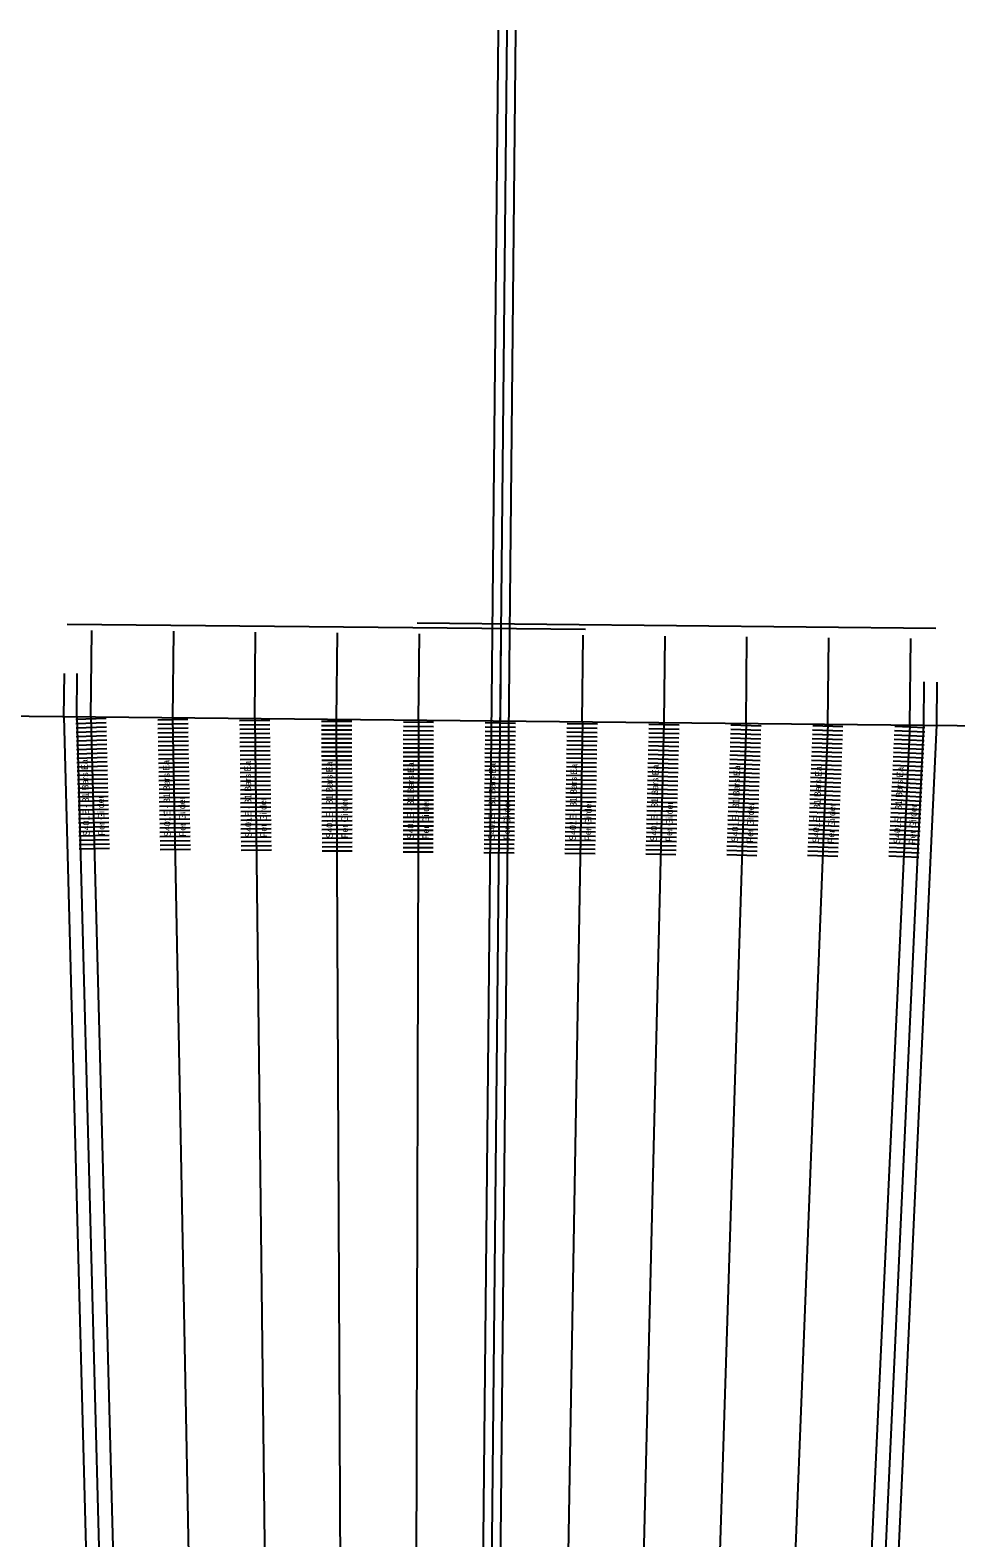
# Model space of a CAD drawing. Extents: x 632276 to 635000, y 381313 to 381846.
# Drawn here: x 634781.2 to 634888.3, y 381526.1 to 381700.5 of the extents above; entities that cross this region are included whole.
import ezdxf

# ---------------------------------------------------------------- set-up
doc = ezdxf.new("R2010")
doc.units = 0
for name, color, linetype in [('B_Boring Annot', 7, 'Continuous'), ('B_No_Plot', 7, 'Continuous'), ('R_Border_Scale', 7, 'Continuous'), ('R_Road Edge of Shoulder', 7, 'Continuous'), ('R_Shade Removal', 7, 'Continuous'), ('R_Wall', 7, 'Continuous')]:
    doc.layers.add(name, color=color, linetype=linetype)

msp = doc.modelspace()

# ---------------------------------------------------------------- linework, layer by layer
at = {"layer": 'B_Boring Annot'}
for p, q in [((634832.38, 381395.62), (634835.41, 381700.49)), ((634834.38, 381395.6), (634837.41, 381700.47)), ((634785.12, 381621.1), (634785.17, 381626.1)), ((634786.62, 381621.09), (634786.67, 381626.09)), ((634884.61, 381620.11), (634884.66, 381625.11)), ((634886.11, 381620.1), (634886.16, 381625.1)), ((634785.12, 381621.1), (634790.93, 381401.03)), ((634786.62, 381621.14), (634792.43, 381401.07)), ((634874.43, 381400.26), (634884.62, 381620.17)), ((634875.93, 381400.19), (634886.11, 381620.1))]:
    msp.add_line(p, q, dxfattribs=at)
at = {"layer": 'B_No_Plot'}
msp.add_line((634671.3, 381622.23), (634999.94, 381618.97), dxfattribs=at)
at = {"layer": 'R_Border_Scale'}
for p, q in [((634785.48, 381631.8), (634845.47, 381631.21)), ((634885.98, 381631.3), (634825.98, 381631.9)), ((634790, 381620.87), (634786.5, 381620.78)), ((634799.47, 381620.76), (634795.97, 381620.69)), ((634808.94, 381620.65), (634805.44, 381620.61)), ((634818.42, 381620.55), (634814.92, 381620.53)), ((634827.89, 381620.44), (634824.39, 381620.45)), ((634790.01, 381620.37), (634786.51, 381620.28)), ((634790.03, 381619.87), (634786.53, 381619.78)), ((634790.04, 381619.37), (634786.54, 381619.28)), ((634790.05, 381618.87), (634786.55, 381618.78)), ((634799.48, 381620.26), (634795.98, 381620.19)), ((634799.49, 381619.76), (634795.99, 381619.69)), ((634799.5, 381619.26), (634796, 381619.19)), ((634799.51, 381618.76), (634796.01, 381618.69)), ((634808.95, 381620.15), (634805.45, 381620.11)), ((634808.96, 381619.65), (634805.46, 381619.61)), ((634808.96, 381619.15), (634805.46, 381619.11)), ((634808.97, 381618.65), (634805.47, 381618.61)), ((634818.42, 381620.05), (634814.92, 381620.03)), ((634818.42, 381619.55), (634814.92, 381619.53)), ((634818.42, 381619.05), (634814.92, 381619.03)), ((634827.88, 381619.44), (634824.38, 381619.45)), ((634827.88, 381618.94), (634824.38, 381618.95)), ((634827.89, 381619.94), (634824.39, 381619.95)), ((634837.35, 381619.33), (634833.85, 381619.37)), ((634837.35, 381618.83), (634833.85, 381618.87)), ((634837.36, 381620.33), (634833.86, 381620.37)), ((634837.36, 381619.83), (634833.86, 381619.87)), ((634846.81, 381619.23), (634843.31, 381619.29)), ((634846.81, 381618.73), (634843.31, 381618.79)), ((634846.82, 381619.73), (634843.32, 381619.79)), ((634846.83, 381620.23), (634843.33, 381620.29)), ((634856.27, 381618.62), (634852.77, 381618.71)), ((634856.28, 381619.12), (634852.78, 381619.21)), ((634856.29, 381619.62), (634852.79, 381619.71)), ((634856.3, 381620.12), (634852.8, 381620.2)), ((634865.74, 381619.01), (634862.24, 381619.12)), ((634865.76, 381619.51), (634862.26, 381619.62)), ((634865.77, 381620.01), (634862.27, 381620.12)), ((634875.21, 381618.91), (634871.71, 381619.04)), ((634875.22, 381619.41), (634871.73, 381619.54)), ((634875.24, 381619.91), (634871.75, 381620.04)), ((634884.68, 381618.8), (634881.18, 381618.96)), ((634884.7, 381619.3), (634881.21, 381619.46)), ((634884.73, 381619.8), (634881.23, 381619.96)), ((634790.07, 381618.37), (634786.57, 381618.28)), ((634790.08, 381617.87), (634786.58, 381617.78)), ((634790.09, 381617.37), (634786.59, 381617.28)), ((634799.52, 381618.26), (634796.02, 381618.19)), ((634799.53, 381617.76), (634796.03, 381617.69)), ((634799.54, 381617.26), (634796.04, 381617.19)), ((634808.97, 381618.15), (634805.47, 381618.11)), ((634808.98, 381617.65), (634805.48, 381617.61)), ((634808.99, 381617.15), (634805.49, 381617.11)), ((634818.42, 381618.55), (634814.92, 381618.53)), ((634818.43, 381618.05), (634814.93, 381618.03)), ((634818.43, 381617.55), (634814.93, 381617.53)), ((634818.43, 381617.05), (634814.93, 381617.03)), ((634827.88, 381618.44), (634824.38, 381618.45)), ((634827.88, 381617.94), (634824.38, 381617.95)), ((634827.88, 381617.44), (634824.38, 381617.45)), ((634827.88, 381616.94), (634824.38, 381616.95)), ((634837.33, 381617.33), (634833.83, 381617.37)), ((634837.34, 381618.33), (634833.84, 381618.37)), ((634837.34, 381617.83), (634833.84, 381617.87)), ((634846.78, 381617.23), (634843.28, 381617.29)), ((634846.79, 381617.73), (634843.29, 381617.79)), ((634846.8, 381618.23), (634843.3, 381618.29)), ((634856.23, 381617.12), (634852.73, 381617.21)), ((634856.24, 381617.62), (634852.74, 381617.71)), ((634856.25, 381618.12), (634852.75, 381618.21)), ((634865.68, 381617.01), (634862.18, 381617.12)), ((634865.69, 381617.51), (634862.2, 381617.62)), ((634865.71, 381618.01), (634862.21, 381618.12)), ((634865.73, 381618.51), (634862.23, 381618.62)), ((634875.13, 381616.91), (634871.63, 381617.04)), ((634875.15, 381617.41), (634871.65, 381617.54)), ((634875.17, 381617.91), (634871.67, 381618.04)), ((634875.19, 381618.41), (634871.69, 381618.54)), ((634884.59, 381616.8), (634881.09, 381616.96)), ((634884.61, 381617.3), (634881.11, 381617.46)), ((634884.63, 381617.8), (634881.14, 381617.96)), ((634884.66, 381618.3), (634881.16, 381618.46)), ((634790.11, 381616.87), (634786.61, 381616.78)), ((634790.12, 381616.37), (634786.62, 381616.28)), ((634790.13, 381615.87), (634786.63, 381615.78)), ((634790.15, 381615.37), (634786.65, 381615.28)), ((634799.55, 381616.76), (634796.05, 381616.69)), ((634799.56, 381616.26), (634796.06, 381616.19)), ((634799.57, 381615.76), (634796.07, 381615.69)), ((634799.58, 381615.26), (634796.08, 381615.19)), ((634808.99, 381616.65), (634805.49, 381616.61)), ((634809, 381616.15), (634805.5, 381616.11)), ((634809, 381615.65), (634805.5, 381615.61)), ((634809.01, 381615.15), (634805.51, 381615.11)), ((634818.43, 381616.55), (634814.93, 381616.53)), ((634818.44, 381616.05), (634814.94, 381616.03)), ((634818.44, 381615.55), (634814.94, 381615.53)), ((634827.87, 381615.44), (634824.37, 381615.45)), ((634827.88, 381616.44), (634824.38, 381616.45)), ((634827.88, 381615.94), (634824.38, 381615.95)), ((634837.31, 381615.33), (634833.81, 381615.37)), ((634837.32, 381616.33), (634833.82, 381616.37)), ((634837.32, 381615.83), (634833.82, 381615.87)), ((634837.33, 381616.83), (634833.83, 381616.87)), ((634846.75, 381615.73), (634843.25, 381615.79)), ((634846.75, 381615.23), (634843.25, 381615.29)), ((634846.76, 381616.23), (634843.26, 381616.29)), ((634846.77, 381616.73), (634843.27, 381616.79)), ((634856.18, 381615.12), (634852.68, 381615.21)), ((634856.19, 381615.62), (634852.69, 381615.71)), ((634856.2, 381616.12), (634852.71, 381616.21)), ((634856.22, 381616.62), (634852.72, 381616.71)), ((634865.63, 381615.51), (634862.13, 381615.63)), ((634865.65, 381616.01), (634862.15, 381616.13)), ((634865.66, 381616.51), (634862.16, 381616.63)), ((634875.07, 381615.41), (634871.57, 381615.55)), ((634875.09, 381615.91), (634871.59, 381616.05)), ((634875.11, 381616.41), (634871.61, 381616.54)), ((634884.52, 381615.3), (634881.02, 381615.47)), ((634884.54, 381615.8), (634881.04, 381615.96)), ((634884.56, 381616.3), (634881.07, 381616.46)), ((634790.16, 381614.87), (634786.66, 381614.78)), ((634790.17, 381614.37), (634786.67, 381614.28)), ((634790.18, 381613.87), (634786.69, 381613.78)), ((634799.59, 381614.76), (634796.09, 381614.69)), ((634799.6, 381614.26), (634796.1, 381614.19)), ((634799.61, 381613.76), (634796.11, 381613.69)), ((634809.02, 381614.65), (634805.52, 381614.61)), ((634809.02, 381614.15), (634805.52, 381614.11)), ((634809.03, 381613.65), (634805.53, 381613.61)), ((634818.44, 381615.05), (634814.94, 381615.03)), ((634818.44, 381614.55), (634814.94, 381614.53)), ((634818.45, 381614.05), (634814.95, 381614.03)), ((634818.45, 381613.55), (634814.95, 381613.53)), ((634827.87, 381614.94), (634824.37, 381614.95)), ((634827.87, 381614.44), (634824.37, 381614.45)), ((634827.87, 381613.94), (634824.37, 381613.95)), ((634827.87, 381613.44), (634824.37, 381613.45)), ((634837.3, 381614.33), (634833.8, 381614.37)), ((634837.3, 381613.83), (634833.8, 381613.87)), ((634837.31, 381614.83), (634833.81, 381614.87)), ((634846.72, 381613.73), (634843.22, 381613.79)), ((634846.73, 381614.23), (634843.23, 381614.29)), ((634846.74, 381614.73), (634843.24, 381614.79)), ((634856.14, 381613.62), (634852.64, 381613.71)), ((634856.16, 381614.12), (634852.66, 381614.21)), ((634856.17, 381614.62), (634852.67, 381614.71)), ((634865.57, 381613.52), (634862.07, 381613.63)), ((634865.58, 381614.02), (634862.08, 381614.13)), ((634865.6, 381614.51), (634862.1, 381614.63)), ((634865.61, 381615.01), (634862.12, 381615.13)), ((634874.99, 381613.41), (634871.49, 381613.55)), ((634875.01, 381613.91), (634871.51, 381614.05)), ((634875.03, 381614.41), (634871.53, 381614.55)), ((634875.05, 381614.91), (634871.55, 381615.05)), ((634884.42, 381613.31), (634880.93, 381613.47)), ((634884.45, 381613.8), (634880.95, 381613.97)), ((634884.47, 381614.3), (634880.97, 381614.47)), ((634884.49, 381614.8), (634881, 381614.97)), ((634790.2, 381613.37), (634786.7, 381613.28)), ((634790.21, 381612.87), (634786.71, 381612.78)), ((634790.22, 381612.37), (634786.73, 381612.28)), ((634790.24, 381611.87), (634786.74, 381611.78)), ((634799.62, 381613.26), (634796.12, 381613.19)), ((634799.63, 381612.76), (634796.13, 381612.69)), ((634799.63, 381612.26), (634796.14, 381612.2)), ((634799.64, 381611.76), (634796.14, 381611.7)), ((634809.03, 381613.15), (634805.53, 381613.11)), ((634809.04, 381612.65), (634805.54, 381612.61)), ((634809.04, 381612.15), (634805.55, 381612.11)), ((634818.45, 381613.05), (634814.95, 381613.03)), ((634818.45, 381612.55), (634814.95, 381612.53)), ((634818.45, 381612.05), (634814.95, 381612.03)), ((634827.86, 381611.94), (634824.36, 381611.95)), ((634827.87, 381612.94), (634824.37, 381612.95)), ((634827.87, 381612.44), (634824.37, 381612.45)), ((634837.28, 381612.33), (634833.78, 381612.37)), ((634837.28, 381611.83), (634833.78, 381611.87)), ((634837.29, 381613.33), (634833.79, 381613.37)), ((634837.29, 381612.83), (634833.79, 381612.87)), ((634846.68, 381611.73), (634843.18, 381611.79)), ((634846.69, 381612.23), (634843.19, 381612.29)), ((634846.7, 381612.73), (634843.2, 381612.79)), ((634846.71, 381613.23), (634843.21, 381613.29)), ((634856.09, 381611.62), (634852.6, 381611.71)), ((634856.11, 381612.12), (634852.61, 381612.21)), ((634856.12, 381612.62), (634852.62, 381612.71)), ((634856.13, 381613.12), (634852.63, 381613.21)), ((634865.52, 381612.02), (634862.02, 381612.13)), ((634865.53, 381612.52), (634862.04, 381612.63)), ((634865.55, 381613.02), (634862.05, 381613.13)), ((634874.93, 381611.91), (634871.43, 381612.05)), ((634874.95, 381612.41), (634871.45, 381612.55)), ((634874.97, 381612.91), (634871.47, 381613.05)), ((634884.36, 381611.81), (634880.86, 381611.97)), ((634884.38, 381612.31), (634880.88, 381612.47)), ((634884.4, 381612.81), (634880.91, 381612.97)), ((634790.25, 381611.37), (634786.75, 381611.28)), ((634790.26, 381610.87), (634786.77, 381610.78)), ((634790.28, 381610.37), (634786.78, 381610.28)), ((634799.65, 381611.26), (634796.15, 381611.2)), ((634799.66, 381610.76), (634796.16, 381610.7)), ((634799.67, 381610.26), (634796.17, 381610.2)), ((634809.05, 381611.65), (634805.55, 381611.61)), ((634809.06, 381611.15), (634805.56, 381611.11)), ((634809.06, 381610.65), (634805.56, 381610.61)), ((634809.07, 381610.15), (634805.57, 381610.11)), ((634818.46, 381611.55), (634814.96, 381611.53)), ((634818.46, 381611.05), (634814.96, 381611.03)), ((634818.46, 381610.55), (634814.96, 381610.53)), ((634818.46, 381610.05), (634814.96, 381610.03)), ((634827.86, 381611.44), (634824.36, 381611.45)), ((634827.86, 381610.94), (634824.36, 381610.95)), ((634827.86, 381610.44), (634824.36, 381610.45)), ((634827.86, 381609.94), (634824.36, 381609.95)), ((634837.26, 381610.33), (634833.76, 381610.37)), ((634837.27, 381611.33), (634833.77, 381611.37)), ((634837.27, 381610.83), (634833.77, 381610.87)), ((634846.66, 381610.23), (634843.16, 381610.29)), ((634846.67, 381610.73), (634843.17, 381610.79)), ((634846.68, 381611.23), (634843.18, 381611.29)), ((634856.06, 381610.12), (634852.56, 381610.21)), ((634856.07, 381610.62), (634852.57, 381610.71)), ((634856.08, 381611.12), (634852.58, 381611.21)), ((634865.46, 381610.02), (634861.96, 381610.13)), ((634865.47, 381610.52), (634861.97, 381610.63)), ((634865.49, 381611.02), (634861.99, 381611.13)), ((634865.5, 381611.52), (634862, 381611.63)), ((634874.85, 381609.91), (634871.36, 381610.05)), ((634874.87, 381610.41), (634871.38, 381610.55)), ((634874.89, 381610.91), (634871.4, 381611.05)), ((634874.91, 381611.41), (634871.41, 381611.55)), ((634884.26, 381609.81), (634880.77, 381609.97)), ((634884.29, 381610.31), (634880.79, 381610.47)), ((634884.31, 381610.81), (634880.81, 381610.97)), ((634884.33, 381611.31), (634880.84, 381611.47)), ((634790.29, 381609.87), (634786.79, 381609.78)), ((634790.3, 381609.37), (634786.8, 381609.28)), ((634790.32, 381608.87), (634786.82, 381608.78)), ((634790.33, 381608.37), (634786.83, 381608.28)), ((634799.68, 381609.76), (634796.18, 381609.7)), ((634799.69, 381609.26), (634796.19, 381609.2)), ((634799.7, 381608.76), (634796.2, 381608.7)), ((634799.71, 381608.26), (634796.21, 381608.2)), ((634809.07, 381609.65), (634805.57, 381609.61)), ((634809.08, 381609.15), (634805.58, 381609.11)), ((634809.09, 381608.65), (634805.59, 381608.61)), ((634818.47, 381609.55), (634814.97, 381609.53)), ((634818.47, 381609.05), (634814.97, 381609.03)), ((634818.47, 381608.55), (634814.97, 381608.53)), ((634827.86, 381609.44), (634824.36, 381609.45)), ((634827.86, 381608.94), (634824.36, 381608.95)), ((634827.86, 381608.44), (634824.36, 381608.45)), ((634837.24, 381608.33), (634833.74, 381608.37)), ((634837.25, 381609.33), (634833.75, 381609.37)), ((634837.25, 381608.83), (634833.75, 381608.87)), ((634837.26, 381609.83), (634833.76, 381609.87)), ((634846.62, 381608.23), (634843.12, 381608.29)), ((634846.63, 381608.73), (634843.13, 381608.79)), ((634846.64, 381609.23), (634843.14, 381609.29)), ((634846.65, 381609.73), (634843.15, 381609.79)), ((634856.01, 381608.12), (634852.51, 381608.21)), ((634856.02, 381608.62), (634852.52, 381608.71)), ((634856.03, 381609.12), (634852.53, 381609.21)), ((634856.04, 381609.62), (634852.55, 381609.71)), ((634865.41, 381608.52), (634861.91, 381608.63)), ((634865.42, 381609.02), (634861.93, 381609.13)), ((634865.44, 381609.52), (634861.94, 381609.63)), ((634874.79, 381608.41), (634871.3, 381608.55)), ((634874.81, 381608.91), (634871.32, 381609.05)), ((634874.83, 381609.41), (634871.34, 381609.55)), ((634884.19, 381608.31), (634880.7, 381608.47)), ((634884.22, 381608.81), (634880.72, 381608.97)), ((634884.24, 381609.31), (634880.74, 381609.47)), ((634790.34, 381607.87), (634786.84, 381607.78)), ((634790.36, 381607.37), (634786.86, 381607.28)), ((634790.37, 381606.87), (634786.87, 381606.78)), ((634799.72, 381607.76), (634796.22, 381607.7)), ((634799.73, 381607.26), (634796.23, 381607.2)), ((634799.74, 381606.76), (634796.24, 381606.7)), ((634809.09, 381608.15), (634805.59, 381608.11)), ((634809.1, 381607.65), (634805.6, 381607.61)), ((634809.1, 381607.15), (634805.6, 381607.11)), ((634809.11, 381606.65), (634805.61, 381606.61)), ((634818.47, 381608.05), (634814.97, 381608.03)), ((634818.48, 381607.55), (634814.98, 381607.53)), ((634818.48, 381607.05), (634814.98, 381607.03)), ((634818.48, 381606.55), (634814.98, 381606.53)), ((634827.85, 381607.94), (634824.35, 381607.95)), ((634827.85, 381607.44), (634824.35, 381607.45)), ((634827.85, 381606.94), (634824.35, 381606.95)), ((634827.85, 381606.44), (634824.35, 381606.45)), ((634837.23, 381607.33), (634833.73, 381607.37)), ((634837.23, 381606.83), (634833.73, 381606.87)), ((634837.24, 381607.83), (634833.74, 381607.87)), ((634846.6, 381606.73), (634843.1, 381606.79)), ((634846.61, 381607.23), (634843.11, 381607.29)), ((634846.62, 381607.73), (634843.12, 381607.79)), ((634855.97, 381606.62), (634852.47, 381606.71)), ((634855.98, 381607.12), (634852.48, 381607.21)), ((634856, 381607.62), (634852.5, 381607.71)), ((634865.34, 381606.52), (634861.85, 381606.63)), ((634865.36, 381607.02), (634861.86, 381607.13)), ((634865.38, 381607.52), (634861.88, 381607.63)), ((634865.39, 381608.02), (634861.89, 381608.13)), ((634874.72, 381606.42), (634871.22, 381606.55)), ((634874.74, 381606.92), (634871.24, 381607.05)), ((634874.76, 381607.41), (634871.26, 381607.55)), ((634874.78, 381607.91), (634871.28, 381608.05)), ((634884.1, 381606.31), (634880.6, 381606.47)), ((634884.12, 381606.81), (634880.63, 381606.97)), ((634884.15, 381607.31), (634880.65, 381607.47)), ((634884.17, 381607.81), (634880.67, 381607.97)), ((634790.38, 381606.37), (634786.88, 381606.28)), ((634790.4, 381605.87), (634786.9, 381605.78)), ((634799.75, 381606.26), (634796.25, 381606.2)), ((634799.76, 381605.76), (634796.26, 381605.7)), ((634809.12, 381606.15), (634805.62, 381606.11)), ((634809.12, 381605.65), (634805.62, 381605.61)), ((634818.48, 381606.05), (634814.98, 381606.03)), ((634818.48, 381605.55), (634814.98, 381605.53)), ((634827.85, 381605.94), (634824.35, 381605.95)), ((634827.85, 381605.44), (634824.35, 381605.45)), ((634837.21, 381605.33), (634833.71, 381605.37)), ((634837.22, 381606.33), (634833.72, 381606.37)), ((634837.21, 381605.83), (634833.72, 381605.87)), ((634846.57, 381605.23), (634843.07, 381605.29)), ((634846.58, 381605.73), (634843.08, 381605.79)), ((634846.59, 381606.23), (634843.09, 381606.29)), ((634855.93, 381605.12), (634852.44, 381605.21)), ((634855.95, 381605.62), (634852.45, 381605.71)), ((634855.96, 381606.12), (634852.46, 381606.21)), ((634865.3, 381605.02), (634861.8, 381605.13)), ((634865.31, 381605.52), (634861.81, 381605.63)), ((634865.33, 381606.02), (634861.83, 381606.13)), ((634874.66, 381604.92), (634871.16, 381605.05)), ((634874.68, 381605.42), (634871.18, 381605.55)), ((634874.7, 381605.92), (634871.2, 381606.05)), ((634884.03, 381604.81), (634880.54, 381604.98)), ((634884.05, 381605.31), (634880.56, 381605.48)), ((634884.08, 381605.81), (634880.58, 381605.98))]:
    msp.add_line(p, q, dxfattribs=at)
at = {"layer": 'R_Road Edge of Shoulder'}
msp.add_line((634833.14, 381371.84), (634836.41, 381700.48), dxfattribs=at)
at = {"layer": 'R_Shade Removal'}
for p, q in [((634788.24, 381621.07), (634788.34, 381631.07)), ((634797.72, 381620.98), (634797.82, 381630.98)), ((634807.19, 381620.88), (634807.29, 381630.88)), ((634816.66, 381620.79), (634816.76, 381630.79)), ((634826.14, 381620.69), (634826.24, 381630.69)), ((634835.61, 381620.6), (634835.71, 381630.6)), ((634845.08, 381620.51), (634845.18, 381630.51)), ((634854.56, 381620.41), (634854.66, 381630.41)), ((634864.03, 381620.32), (634864.13, 381630.32)), ((634873.51, 381620.22), (634873.6, 381630.22)), ((634882.99, 381620.13), (634883.09, 381630.13)), ((634788.24, 381621.07), (634794.06, 381401)), ((634801.93, 381400.92), (634797.72, 381620.98)), ((634807.19, 381620.88), (634809.81, 381400.85)), ((634817.68, 381400.77), (634816.66, 381620.79)), ((634826.14, 381620.69), (634825.55, 381400.69)), ((634845.1, 381620.51), (634841.3, 381400.53)), ((634849.18, 381400.45), (634854.57, 381620.41)), ((634864.04, 381620.32), (634857.05, 381400.38)), ((634864.93, 381400.3), (634873.52, 381620.22)), ((634882.99, 381620.13), (634872.8, 381400.22))]:
    msp.add_line(p, q, dxfattribs=at)

# ---------------------------------------------------------------- texts
at = {"layer": 'R_Wall'}
for s, rotation, p in [('S401E - 31 Bars Ea,', 91.5228, (634788.11, 381607.31)), ('S401E - 31 Bars Ea,', 91.1068, (634797.48, 381607.22)), ('S401E - 31 Bars Ea,', 90.6907, (634806.85, 381607.13)), ('S401E - 31 Bars Ea,', 90.2744, (634816.23, 381607.04)), ('S401E - 31 Bars Ea,', 89.858, (634825.6, 381606.95)), ('S401E - 31 Bars Ea,', 89.4304, (634834.98, 381606.86)), ('S401E - 31 Bars Ea,', 89.0185, (634844.35, 381606.77)), ('S401E - 31 Bars Ea,', 88.6021, (634853.72, 381606.68)), ('S401E - 31 Bars Ea,', 88.19, (634863.1, 381606.59)), ('S401E - 31 Bars Ea,', 87.7697, (634872.47, 381606.5)), ('S401E - 31 Bars Ea,', 87.3558, (634881.85, 381606.42)), ('Per Girder', 91.5228, (634789.86, 381607.36)), ('Per Girder', 91.1068, (634799.23, 381607.25)), ('Per Girder', 90.6907, (634808.6, 381607.15)), ('Per Girder', 90.2744, (634817.98, 381607.04)), ('Per Girder', 89.858, (634827.35, 381606.94)), ('Per Girder', 89.4304, (634836.73, 381606.84)), ('Per Girder', 89.0185, (634846.1, 381606.74)), ('Per Girder', 88.6021, (634855.47, 381606.64)), ('Per Girder', 88.19, (634864.84, 381606.54)), ('Per Girder', 87.7697, (634874.22, 381606.44)), ('Per Girder', 87.3558, (634883.6, 381606.34))]:
    msp.add_text(s, height=0.75, rotation=rotation, dxfattribs=at).set_placement(p)

doc.saveas('drawing.dxf')
